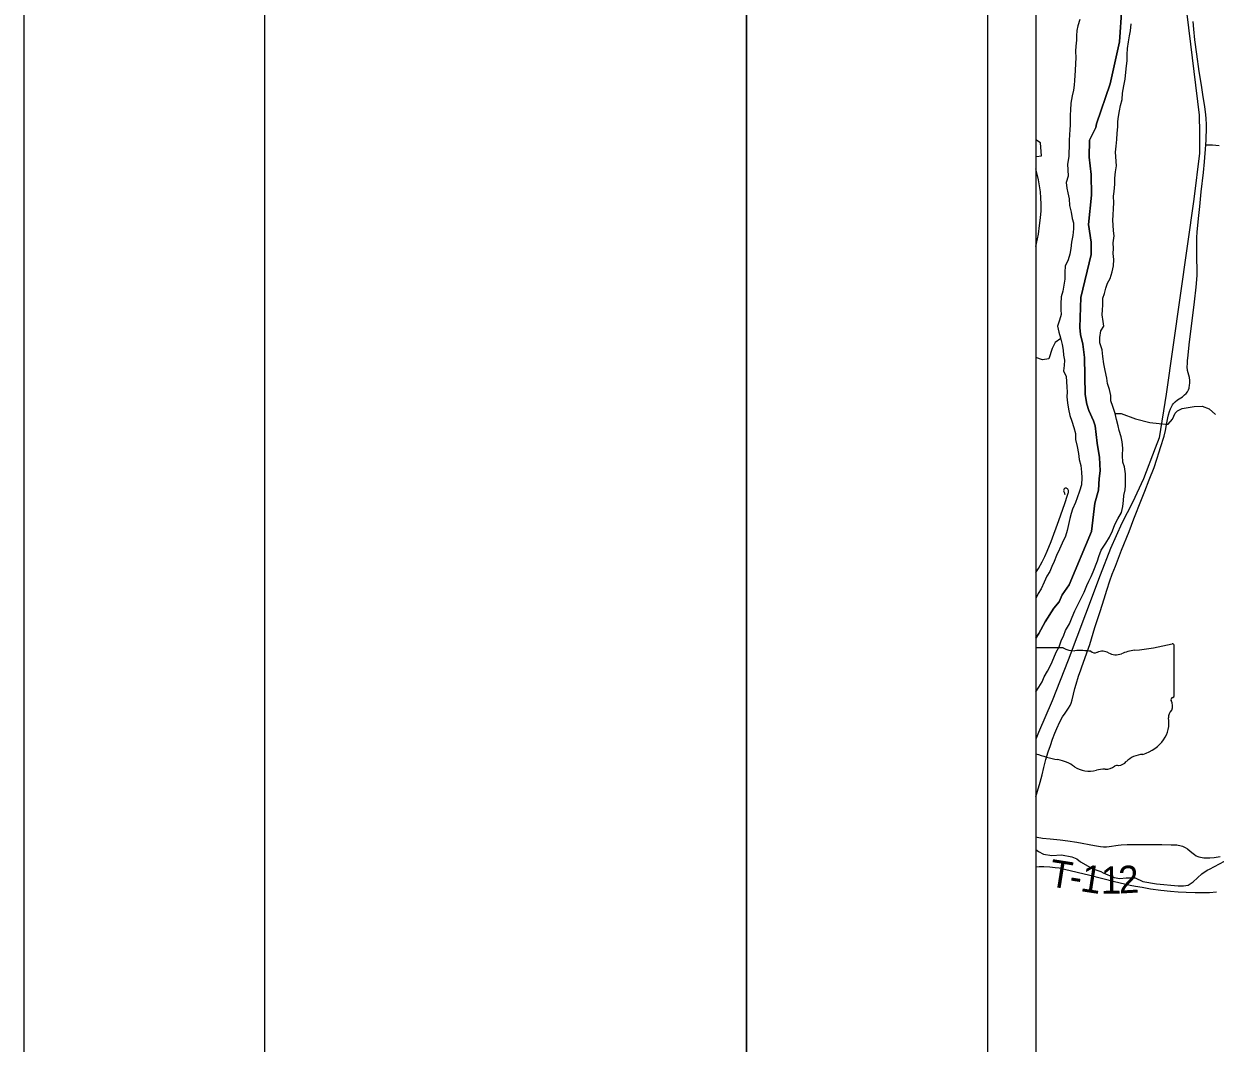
# Model space of a CAD drawing. Extents: x 0 to 34, y 0 to 22.
# Drawn here: x 0 to 2.472, y 17.641 to 19.758 of the extents above; entities that cross this region are included whole.
import ezdxf

# ---------------------------------------------------------------- set-up
doc = ezdxf.new("R2010")
doc.units = 0
for name, color, linetype in [('GM_X_Major_River', 7, 'Continuous'), ('GM_X_Minor_River', 7, 'Continuous'), ('GM_X_Rail_Line', 7, 'Continuous'), ('GM_X_State_Location', 7, 'Continuous'), ('GM_X_State_Route', 7, 'Continuous'), ('GM_X_Township_Road', 7, 'Continuous'), ('GM_X_Township_Road_Text', 7, 'Continuous'), ('GM_X_Township_Text', 7, 'Continuous'), ('SH_Border', 7, 'Continuous'), ('SH_Cut_Line', 7, 'Continuous'), ('SH_Data', 7, 'Continuous')]:
    doc.layers.add(name, color=color, linetype=linetype)

msp = doc.modelspace()

# ---------------------------------------------------------------- linework, layer by layer
at = {"layer": 'GM_X_Major_River'}
for points in [[(2.1915, 19.7663), (2.1874, 19.753), (2.1856, 19.7435), (2.1849, 19.7329), (2.1846, 19.7235), (2.1835, 19.7113), (2.1828, 19.7007), (2.1833, 19.6871), (2.1823, 19.6753), (2.1816, 19.6609), (2.1809, 19.6503), (2.1802, 19.6401), (2.1795, 19.6302), (2.1781, 19.6196), (2.1755, 19.6082), (2.173, 19.5927), (2.1719, 19.5783), (2.1716, 19.5684), (2.1717, 19.5575), (2.1714, 19.5476), (2.1711, 19.5374), (2.1704, 19.5279), (2.1697, 19.5154), (2.1694, 19.5014), (2.1687, 19.4911), (2.1684, 19.4817)], [(2.2655, 19.4907), (2.2669, 19.5036), (2.2684, 19.5176), (2.269, 19.5305), (2.2701, 19.5438), (2.2704, 19.5544), (2.2718, 19.565), (2.2737, 19.5771), (2.2762, 19.5877), (2.2795, 19.6006), (2.2802, 19.6135), (2.2828, 19.6287), (2.2853, 19.6424), (2.2867, 19.6568), (2.2885, 19.67), (2.2896, 19.681), (2.2899, 19.6939), (2.2906, 19.7064), (2.2924, 19.7201), (2.2949, 19.7326), (2.2968, 19.7432), (2.2982, 19.7576)], [(2.1, 18.3702), (2.1063, 18.3799), (2.1131, 18.3909), (2.1176, 18.4015), (2.1244, 18.4136), (2.1323, 18.4277), (2.1376, 18.441), (2.1425, 18.4527), (2.1489, 18.4641), (2.1527, 18.4763), (2.1584, 18.488), (2.1617, 18.4979), (2.17, 18.5115), (2.1753, 18.5252), (2.181, 18.5389), (2.1874, 18.5514), (2.1927, 18.562), (2.2006, 18.5772), (2.2062, 18.5909), (2.21, 18.6003), (2.2149, 18.6098), (2.2194, 18.6193), (2.2285, 18.6421), (2.2307, 18.6516), (2.2356, 18.6645), (2.2458, 18.6789), (2.253, 18.6914), (2.2594, 18.7047), (2.2643, 18.718), (2.2704, 18.7297), (2.2779, 18.7426), (2.2805, 18.7552), (2.2824, 18.7677), (2.2828, 18.7783), (2.2858, 18.7897), (2.2865, 18.7991), (2.2865, 18.8113), (2.2861, 18.8234), (2.2842, 18.8374), (2.2808, 18.8476), (2.2804, 18.8609), (2.2811, 18.8765), (2.2796, 18.8897), (2.2773, 18.8996), (2.2735, 18.9132), (2.2708, 18.9227), (2.2678, 18.9359), (2.2651, 18.9481), (2.2598, 18.9632), (2.2556, 18.975), (2.2556, 18.9856), (2.2533, 18.9981), (2.2492, 19.0106), (2.2476, 19.0216), (2.2438, 19.0375), (2.2415, 19.0515), (2.2392, 19.067), (2.2377, 19.0803), (2.2332, 19.0954), (2.2328, 19.1061), (2.235, 19.1201), (2.2411, 19.1296), (2.2399, 19.1391), (2.2376, 19.1535), (2.2387, 19.1637), (2.2395, 19.1735), (2.2395, 19.188), (2.2428, 19.1974), (2.2455, 19.2088), (2.2489, 19.2191), (2.2545, 19.2289), (2.2587, 19.2422), (2.2617, 19.2547), (2.262, 19.268), (2.2605, 19.2805), (2.2616, 19.2907), (2.2609, 19.3029), (2.2627, 19.3173), (2.2612, 19.3279), (2.2604, 19.3396), (2.26, 19.3499), (2.2604, 19.3601), (2.2611, 19.3741), (2.2619, 19.3859), (2.2615, 19.3995), (2.263, 19.409), (2.2645, 19.4245), (2.2641, 19.4371), (2.2656, 19.4503), (2.2674, 19.4628), (2.2655, 19.4907)], [(2.1684, 19.4817), (2.1661, 19.4664), (2.1668, 19.4543), (2.1672, 19.4414), (2.1631, 19.4277), (2.1643, 19.416), (2.1669, 19.4065), (2.1692, 19.394), (2.1704, 19.3804), (2.1734, 19.3667), (2.1757, 19.3535), (2.1783, 19.344), (2.1787, 19.3315), (2.1772, 19.3182), (2.1746, 19.3042), (2.1727, 19.2913), (2.1705, 19.2795), (2.1671, 19.2674), (2.1611, 19.2541), (2.1607, 19.2416), (2.1607, 19.2276), (2.1585, 19.2151), (2.1566, 19.2026), (2.1528, 19.1908), (2.1521, 19.1764), (2.1521, 19.1639), (2.1525, 19.154), (2.1491, 19.1419), (2.1454, 19.1294), (2.148, 19.1172), (2.1514, 19.1055), (2.1552, 19.0915), (2.1572, 19.0797), (2.1579, 19.0695), (2.1595, 19.0589), (2.1587, 19.0483), (2.1576, 19.0373), (2.1629, 19.0255), (2.1641, 19.0149), (2.1644, 19.0028), (2.1652, 18.9933), (2.1649, 18.9831), (2.166, 18.9702), (2.1683, 18.9573), (2.171, 18.9441), (2.1748, 18.9323), (2.1793, 18.9194), (2.1824, 18.9069), (2.1824, 18.8941), (2.1862, 18.8797), (2.1885, 18.8656), (2.1904, 18.8531), (2.1934, 18.8402), (2.1953, 18.8262), (2.1957, 18.8145), (2.195, 18.8005), (2.1908, 18.7868), (2.1863, 18.7731), (2.1826, 18.7637), (2.1765, 18.75), (2.1735, 18.7405), (2.1705, 18.7303), (2.1682, 18.7178), (2.1652, 18.7056), (2.1615, 18.6935), (2.1551, 18.6794), (2.1494, 18.6665), (2.1434, 18.6536), (2.1385, 18.6407), (2.1332, 18.6309), (2.1291, 18.6202), (2.123, 18.6108), (2.1174, 18.5979), (2.1113, 18.5846), (2.1053, 18.5743), (2.1, 18.5645), (2.1, 18.5645)]]:
    msp.add_lwpolyline(points, dxfattribs=at)
at = {"layer": 'GM_X_Minor_River'}
msp.add_line((2.1, 19.4835), (2.1019, 19.4821), dxfattribs=at)
for points in [[(2.1019, 19.4821), (2.1117, 19.4837), (2.11, 19.5106), (2.1, 19.5169)], [(2.1519, 19.1039), (2.1405, 19.0959), (2.1338, 19.0834), (2.1275, 19.0617), (2.1138, 19.0601), (2.1, 19.0647)], [(2.2651, 18.9482), (2.2771, 18.9486), (2.307, 18.937), (2.3365, 18.9296), (2.3691, 18.9259), (2.3751, 18.9264), (2.3842, 18.9367), (2.3894, 18.9488), (2.3943, 18.9542), (2.4037, 18.9584), (2.4291, 18.9627), (2.4453, 18.9636), (2.4597, 18.9583), (2.473, 18.9466)], [(2.1, 18.043), (2.1061, 18.0386), (2.1159, 18.0333), (2.1333, 18.0308), (2.1534, 18.032), (2.175, 18.028), (2.1852, 18.0235), (2.1932, 18.0171), (2.2182, 18.0031), (2.2349, 17.9972), (2.2398, 17.9945), (2.2629, 17.9848), (2.2743, 17.9829), (2.2875, 17.9845), (2.3061, 17.9839), (2.3224, 17.9767), (2.3504, 17.9716), (2.3958, 17.9673), (2.4064, 17.9673), (2.4162, 17.9693), (2.4268, 17.9762), (2.4448, 17.9926), (2.4558, 18.0002), (2.4607, 18.0025), (2.492, 18.0187)]]:
    msp.add_lwpolyline(points, dxfattribs=at)
at = {"layer": 'GM_X_Rail_Line'}
for points in [[(2.1, 20.4677), (2.1, 18.4819), (2.1068, 18.4912), (2.1195, 18.5155), (2.1375, 18.5444), (2.1484, 18.557), (2.1551, 18.5715), (2.1694, 18.5924), (2.2158, 18.7034), (2.2226, 18.7623), (2.2301, 18.7889), (2.2314, 18.8131), (2.234, 18.8291), (2.2327, 18.8568), (2.2273, 18.8871), (2.2233, 18.9227), (2.2202, 18.9333), (2.2099, 18.9549), (2.2061, 18.9678), (2.2029, 18.9879), (2.201, 19.0645), (2.1979, 19.0922), (2.1929, 19.1122), (2.1916, 19.1266), (2.1936, 19.1892), (2.2151, 19.2785), (2.2149, 19.3039), (2.2098, 19.3407), (2.2156, 19.4014), (2.215, 19.4443), (2.211, 19.4807), (2.2116, 19.5156), (2.2247, 19.5424), (2.2258, 19.5501), (2.2548, 19.633), (2.2736, 19.7201), (2.2784, 19.7904)], [(2.3772, 20.0785), (2.4395, 19.568), (2.4402, 19.531), (2.4396, 19.4892), (2.4278, 19.3931), (2.3704, 18.9887), (2.3559, 18.898), (2.3477, 18.8762), (2.324, 18.8124), (2.3006, 18.7639), (2.2785, 18.7205), (2.2549, 18.6677), (2.2339, 18.613), (2.203, 18.532), (2.1674, 18.436), (2.1344, 18.3519), (2.106, 18.2857), (2.1, 18.2718)], [(2.2784, 19.7904), (2.2736, 19.7201), (2.2548, 19.633), (2.2258, 19.5501), (2.2247, 19.5424), (2.2116, 19.5156), (2.211, 19.4807), (2.215, 19.4443), (2.2156, 19.4014), (2.2098, 19.3407), (2.2149, 19.3039), (2.2151, 19.2785), (2.1936, 19.1892), (2.1916, 19.1266), (2.1929, 19.1122), (2.1979, 19.0922), (2.201, 19.0645), (2.2029, 18.9879), (2.2061, 18.9678), (2.2099, 18.9549), (2.2202, 18.9333), (2.2233, 18.9227), (2.2273, 18.8871), (2.2327, 18.8568), (2.234, 18.8291), (2.2314, 18.8131), (2.2301, 18.7889), (2.2226, 18.7623), (2.2158, 18.7034), (2.1694, 18.5924), (2.1551, 18.5715), (2.1484, 18.557), (2.1375, 18.5444), (2.1195, 18.5155), (2.1068, 18.4912), (2.1, 18.4819), (2.1, 15.4153)], [(2.1, 19.2953), (2.1014, 19.3016), (2.1055, 19.3204), (2.1081, 19.3384), (2.1102, 19.3547), (2.1113, 19.3695), (2.1113, 19.3829), (2.1108, 19.3961), (2.1099, 19.4087), (2.108, 19.4214), (2.1056, 19.4339), (2.1028, 19.4456), (2.1, 19.4567)], [(2.1, 18.0067), (2.1072, 18.0074), (2.117, 18.0076), (2.1295, 18.007), (2.1401, 18.0059), (2.1486, 18.0048), (2.1594, 18.0025), (2.2124, 17.9895), (2.2635, 17.9765), (2.2841, 17.9718), (2.2962, 17.9692), (2.3068, 17.967), (2.3206, 17.9646), (2.3381, 17.9616), (2.3598, 17.9588), (2.3798, 17.9567), (2.3955, 17.9554), (2.4125, 17.9544), (2.4309, 17.9537), (2.4459, 17.9535), (2.4604, 17.954), (2.475, 17.9548)]]:
    msp.add_lwpolyline(points, dxfattribs=at)
at = {"layer": 'GM_X_State_Route'}
msp.add_lwpolyline([(2.1, 18.1523), (2.104, 18.1644), (2.1094, 18.1829), (2.1131, 18.1979), (2.1171, 18.2134), (2.1212, 18.23), (2.1257, 18.2457), (2.1304, 18.2593), (2.1351, 18.2721), (2.1397, 18.2847), (2.1437, 18.2943), (2.1499, 18.3079), (2.1559, 18.3186), (2.1609, 18.3264), (2.1681, 18.3366), (2.1716, 18.3422), (2.1733, 18.3466), (2.1755, 18.3539), (2.1812, 18.3774), (2.1836, 18.3865), (2.1891, 18.4028), (2.1936, 18.4163), (2.1957, 18.4226), (2.2122, 18.4687), (2.2228, 18.5039), (2.2335, 18.5372), (2.2421, 18.5638), (2.2476, 18.5815), (2.2537, 18.6011), (2.2584, 18.6144), (2.2653, 18.6317), (2.2783, 18.6647), (2.2939, 18.7034), (2.3036, 18.7296), (2.3195, 18.7699), (2.3265, 18.7872), (2.3357, 18.8103), (2.3455, 18.8365), (2.3513, 18.8536), (2.3563, 18.8689), (2.3589, 18.8778), (2.3664, 18.901), (2.3693, 18.9133), (2.3723, 18.9288), (2.3742, 18.9395), (2.3755, 18.9456), (2.3773, 18.9525), (2.3795, 18.9582), (2.3808, 18.961), (2.3822, 18.9636), (2.3837, 18.9662), (2.3855, 18.9686), (2.3875, 18.9708), (2.3897, 18.9728), (2.3945, 18.9767), (2.4044, 18.9831), (2.409, 18.9868), (2.4125, 18.99), (2.4147, 18.9932), (2.4169, 18.9974), (2.4182, 19.0013), (2.4191, 19.0079), (2.4195, 19.011), (2.4197, 19.0141), (2.4197, 19.0172), (2.419, 19.0234), (2.4152, 19.0376), (2.4145, 19.045), (2.4147, 19.0524), (2.415, 19.0581), (2.4154, 19.0635), (2.4192, 19.0969), (2.4216, 19.1184), (2.4296, 19.18), (2.4332, 19.2109), (2.4352, 19.2349), (2.4354, 19.2502), (2.4344, 19.2677), (2.4342, 19.2955), (2.4346, 19.3133), (2.4354, 19.3256), (2.4388, 19.3596), (2.4406, 19.378), (2.4437, 19.4088), (2.4479, 19.4489), (2.4502, 19.4708), (2.4528, 19.5063), (2.4534, 19.5163), (2.4537, 19.5193), (2.4542, 19.5394), (2.4542, 19.5488), (2.4534, 19.5606), (2.4527, 19.5688), (2.4507, 19.5856), (2.4478, 19.606), (2.4438, 19.6304), (2.4394, 19.6585), (2.4342, 19.6946), (2.4305, 19.7244), (2.4283, 19.7461), (2.4265, 19.7621)], dxfattribs=at)
at = {"layer": 'GM_X_Township_Road'}
for points in [[(2.4528, 19.5063), (2.4666, 19.506), (2.4805, 19.505)], [(2.1, 18.6179), (2.1055, 18.6267), (2.1132, 18.6401), (2.1188, 18.6511), (2.1239, 18.6623), (2.1318, 18.6825), (2.1483, 18.726), (2.1566, 18.7494), (2.1604, 18.7612), (2.1658, 18.7789), (2.1672, 18.7827), (2.1677, 18.7844), (2.1679, 18.7859), (2.168, 18.7873), (2.1677, 18.7887), (2.1673, 18.79), (2.1665, 18.7912), (2.1657, 18.7922), (2.1647, 18.7928), (2.1636, 18.7931), (2.1624, 18.7933), (2.1611, 18.793), (2.1599, 18.7925), (2.1591, 18.7917), (2.1584, 18.7908), (2.1581, 18.7893), (2.158, 18.788), (2.1582, 18.7867), (2.1588, 18.7848), (2.1607, 18.78)], [(2.1, 18.0691), (2.1029, 18.0686), (2.1144, 18.0667), (2.1299, 18.0653), (2.1509, 18.0631), (2.1666, 18.0609), (2.1852, 18.0581), (2.222, 18.0516), (2.2342, 18.0494), (2.2404, 18.0488), (2.2466, 18.0488), (2.2527, 18.0494), (2.271, 18.0523), (2.2772, 18.0529), (2.2896, 18.0535), (2.2958, 18.0536), (2.3059, 18.0536), (2.3273, 18.0536), (2.3462, 18.0536), (2.3618, 18.0535), (2.381, 18.053), (2.3894, 18.0527), (2.3927, 18.0526), (2.3959, 18.0523), (2.3993, 18.0516), (2.4019, 18.0509), (2.4047, 18.0498), (2.4072, 18.0488), (2.41, 18.0475), (2.415, 18.0442), (2.4204, 18.0398), (2.4265, 18.0348), (2.4293, 18.0325), (2.4332, 18.0299), (2.4361, 18.0286), (2.4387, 18.0277), (2.4417, 18.0268), (2.4453, 18.0262), (2.4492, 18.0256), (2.4543, 18.0254), (2.4616, 18.0256), (2.4702, 18.0267), (2.4826, 18.0287)]]:
    msp.add_lwpolyline(points, dxfattribs=at)
at = {"layer": 'GM_X_Township_Text'}
for points in [[(2.1572, 18.462), (2.1, 18.462), (2.1, 18.2419)], [(2.387, 18.3623), (2.387, 18.3623), (2.3871, 18.3623), (2.3871, 18.4672)]]:
    msp.add_lwpolyline(points, dxfattribs=at)
for centre, major_axis, start_param, end_param in [((2.2697, 18.7349), (0.3495, 0), 4.814394, 5.042369), ((2.3834, 18.4674), (0.00367, 0), 6.197627, 7.989034), ((2.1802, 18.4853), (0.037, 0), 4.042888, 4.731792), ((2.1925, 18.3497), (0.133, 0), 1.404758, 1.657859), ((2.2227, 18.4601), (0.0107, 0), 3.836095, 5.185415), ((2.2384, 18.4369), (0.0222, 0), 0.950623, 2.079405), ((2.267, 18.4687), (0.0267, 0), 4.08156, 5.145723), ((2.3142, 18.4009), (0.0703, 0), 1.699012, 2.107814), ((2.3862, 18.3546), (0.00568, 0), 1.883978, 3.671073), ((2.3501, 18.3414), (0.0341, 0), 5.934695, 6.695948), ((2.3831, 18.3619), (0.00393, 0), 5.05454, 6.418171), ((2.4002, 18.3185), (0.0248, 0), 2.387724, 3.262537), ((2.2892, 18.3052), (0.0874, 0), 5.101753, 6.440018), ((2.2017, 18.4267), (0.2524, 0), 4.297647, 4.488961), ((2.1265, 18.1686), (0.079, 0), 0.823519, 1.323587), ((2.2654, 18.2391), (0.0282, 0), 4.937069, 5.64225), ((2.3261, 18.2023), (0.0479, 0), 1.647645, 2.488434), ((2.2119, 18.2459), (0.0501, 0), 4.026481, 4.996735), ((2.2408, 18.1767), (0.0412, 0), 1.495662, 1.94098), ((2.2445, 18.2309), (0.0267, 0), 4.691044, 5.507374), ((2.2686, 18.2116), (0.00752, 0), 1.147584, 2.315152)]:
    msp.add_ellipse(centre, major_axis=major_axis, ratio=0.8, start_param=start_param, end_param=end_param, dxfattribs=at)
at = {"layer": 'SH_Border'}
for points in [[(0.5, 21.5), (1.5, 21.5), (1.5, 0.5), (0.5, 0.5)], [(1.5, 21.5), (33.5, 21.5), (33.5, 0.5), (1.5, 0.5)]]:
    msp.add_lwpolyline(points, close=True, dxfattribs=at)
at = {"layer": 'SH_Cut_Line'}
msp.add_lwpolyline([(0, 0), (34, 0), (34, 22), (0, 22)], close=True, dxfattribs=at)
at = {"layer": 'SH_Data'}
for p, q in [((2, 21), (2, 14)), ((2.1, 20.9), (2.1, 14.1))]:
    msp.add_line(p, q, dxfattribs=at)

# ---------------------------------------------------------------- texts
at = {"layer": 'GM_X_State_Location'}
msp.add_text('666', height=0.000189, rotation=0, dxfattribs=at).set_placement((2.1517, 18.3315))
for s in ['s', 'r']:
    msp.add_text(s, height=0.000189, dxfattribs=at).set_placement((2.2186, 18.3452))
at = {"layer": 'GM_X_Township_Road_Text'}
for s, rotation, p in [('T', 350.9886, (2.1253, 17.9671)), ('1', 351.4356, (2.1908, 17.9568)), ('1', 0.7209, (2.2354, 17.9509)), ('2', 3.359, (2.2732, 17.9514)), ('-', 351.0717, (2.1673, 17.9605))]:
    msp.add_text(s, height=0.0568, rotation=rotation, dxfattribs=at).set_placement(p)

doc.saveas('drawing.dxf')
